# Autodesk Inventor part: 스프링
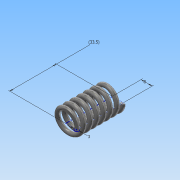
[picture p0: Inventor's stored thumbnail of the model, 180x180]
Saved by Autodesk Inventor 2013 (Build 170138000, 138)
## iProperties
Created: 2019-11
Part Number: 스프링
Material: 스테인리스강
Document SubType Name: Modeling
Designer: Administrator
Density: 8.08 g/cm^3
Mass: 19.7195 g
Surface Area: 33.0743 cm^2
Volume: 2.44053 cm^3
Author: Administrator
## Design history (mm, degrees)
sketch "스케치1"
  geometry: L1 (0, 0)-(-8, 0); L2 (-8, 0)-(-8, 33.5); L3 (-8, 33.5)-(0, 33.5); L4 (0, 33.5)-(0, 0); C1 r 1.5 at (0, 0)
  constraints: 8 end point, 2 parallel, 1 centre point, 1 coincident, 1 horizontal, 1 perpendicular
  dimensions: "d4" = 8 distance of L2.end L3.end; "d6" = 33.5 distance of L1.end L2.end (derived); "d7" = 3 diameter of C1
feature "코일1" pitch "d8" = 10; turns "d10" = 7; dims "d9" = 33.5 (= d6), "d11" = 0, angle "d12" = 90 deg, angle "d13" = 90 deg, "d14" = 0, "d15" = 0
sketch "스케치2"
  geometry: L1 (-40.508, 0)-(32.701, 0); L2 (32.701, 0)-(32.701, 33.5); L3 (32.701, 33.5)-(-40.508, 33.5); L4 (-40.508, 33.5)-(-40.508, 0); 1 further point
  constraints: 8 end point, 2 parallel, 1 horizontal, 1 perpendicular
  dimensions: "d16" = 0 distance from line of point (0, 0) L1; "d17" = 33.5 distance of L1.end L2.end (= d6)
extrude "돌출1" sketch "스케치2" stored distance "d18" = 40; taper "d19" = 0 deg
node "솔리드1"
